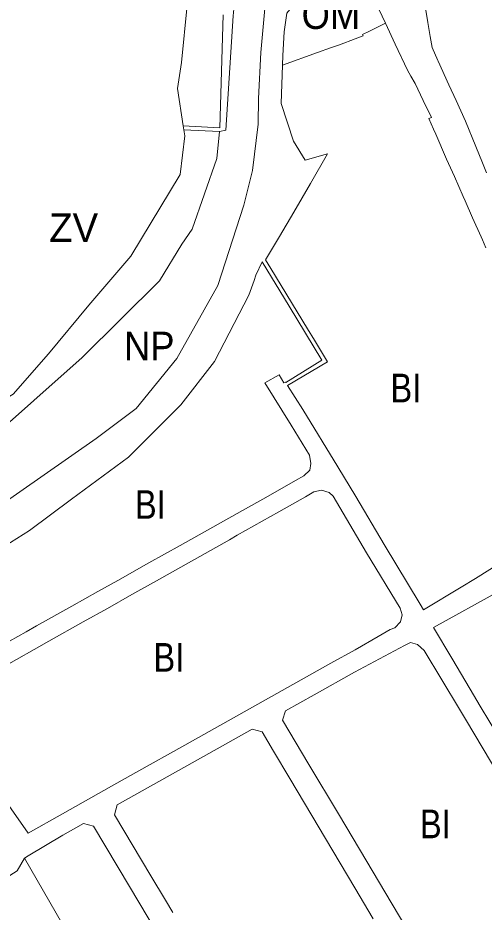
# Model space of a CAD drawing. Extents: x -650451 to -642268, y -1075216 to -1066610.
# Drawn here: x -646131.4 to -645935.9, y -1070484.4 to -1070109.3 of the extents above; entities that cross this region are included whole.
import ezdxf

# ---------------------------------------------------------------- set-up
doc = ezdxf.new("R2010")
doc.units = 0
doc.header["$LTSCALE"] = 4.8
for name, color, linetype, lineweight in [('1', 7, 'Continuous', 13), ('12', 7, 'Continuous', 13), ('15', 7, 'Continuous', 13), ('2', 7, 'Continuous', 13), ('24', 7, 'Continuous', 13), ('40', 7, 'Continuous', 13), ('45', 7, 'Continuous', 13), ('48', 7, 'Continuous', 13)]:
    doc.layers.add(name, color=color, linetype=linetype, lineweight=lineweight)
doc.layers.add('62', color=7, linetype='Continuous')

msp = doc.modelspace()

# ---------------------------------------------------------------- linework, layer by layer
at = {"layer": '1'}
for points in [[(-646164.402, -1070484.923), (-646164.216, -1070484.38), (-646164.005, -1070483.851), (-646163.769, -1070483.337), (-646163.51, -1070482.84), (-646161.74, -1070481.82), (-646156.91, -1070483.01), (-646134.79, -1070469.05), (-646131.7, -1070467.11), (-646128.68, -1070461.77)], [(-646128.68, -1070461.77), (-646112.64, -1070489.39), (-646100.45, -1070509.84), (-646087.81, -1070531.49), (-646077.92, -1070548.62), (-646061.11, -1070577.5), (-646060.88, -1070577.9)]]:
    msp.add_lwpolyline(points, dxfattribs=at)
at = {"layer": '12'}
for points in [[(-646020.39, -1070129.18), (-646020.23, -1070125.05), (-646019.71, -1070115.15), (-646018.64, -1070107.32), (-646014.13, -1070101.92), (-646006.74, -1070098.07), (-646002.8, -1070097.37), (-645992.6, -1070095.69), (-645985.08, -1070094.46)], [(-645985.08, -1070094.46), (-645984.1, -1070097.01), (-645977.22, -1070111.51)], [(-645977.22, -1070111.51), (-645983.92, -1070114.9), (-645986.83, -1070116.33), (-645986.61, -1070116.88), (-645989.89, -1070118.09), (-645996.56, -1070120.56), (-646000.31, -1070121.94), (-646005.76, -1070123.86), (-646020.39, -1070129.18)]]:
    msp.add_lwpolyline(points, dxfattribs=at)
at = {"layer": '15'}
for points in [[(-646159.26, -1070328.75), (-646152.57, -1070323.39), (-646098.57, -1070285.71), (-646081.74, -1070273.1), (-646064.78, -1070252.22), (-646047.55, -1070221.59), (-646036.61, -1070187.84), (-646033.06, -1070173.32), (-646030.66, -1070153.86), (-646030.51, -1070143.17), (-646029.45, -1070123.88), (-646027.66, -1070103.79), (-646016.12, -1070093.28), (-646003.08, -1070088.07), (-645995.59, -1070086.74), (-646003.18, -1070084.88), (-646023.84, -1070078.03), (-646027.71, -1070080.48)], [(-646027.71, -1070080.48), (-646032.79, -1070084.73), (-646040.05, -1070097.06), (-646041.14, -1070108.39), (-646044.21, -1070156.41), (-646046.84, -1070157.03), (-646061.8, -1070156.29), (-646062.06, -1070154.56)], [(-645985.08, -1070094.46), (-645992.6, -1070095.69), (-646002.8, -1070097.37), (-646006.74, -1070098.07), (-646014.13, -1070101.92), (-646018.64, -1070107.32), (-646019.71, -1070115.15), (-646020.23, -1070125.05), (-646020.39, -1070129.18)], [(-646062.06, -1070154.56), (-646046.76, -1070155.43), (-646045.35, -1070108.04)], [(-646020.39, -1070129.18), (-646021, -1070145.27), (-646015.86, -1070161.08), (-646010.94, -1070168.93), (-646001.55, -1070166.34), (-646008.75, -1070178.83), (-646015.63, -1070190.78), (-646021.68, -1070200.97), (-646027.5, -1070210.78), (-646025.32, -1070214.44), (-646009.96, -1070239.67), (-646006.95, -1070244.46), (-646001.55, -1070253.52), (-646018.27, -1070263.54), (-646011.89, -1070273.62), (-645997.17, -1070297.57), (-645989.72, -1070310.12), (-645977.73, -1070330.16), (-645962.69, -1070355.25), (-645961.29, -1070357.59), (-645945.44, -1070348.04), (-645939.51, -1070344.47), (-645927.52, -1070336.95)], [(-646170.01, -1070390.33), (-646127.93, -1070366.76), (-646123.57, -1070364.32), (-646108.74, -1070356.01), (-646097.91, -1070349.95), (-646089.54, -1070345.26), (-646076.45, -1070337.93), (-646063.37, -1070330.6), (-646037.19, -1070315.94), (-646027.47, -1070310.49), (-646014.98, -1070303.38), (-646011.51, -1070301.37), (-646008.91, -1070299.03), (-646008.5, -1070296.25), (-646009.17, -1070292.79), (-646016.79, -1070280.17), (-646027.85, -1070262.42), (-646021.85, -1070259.08), (-646019.81, -1070262.45), (-646019.19, -1070262.09), (-646019.06, -1070262.29), (-646003.89, -1070252.88), (-646017.67, -1070230.24), (-646029, -1070211.63), (-646031.59, -1070217.26), (-646032.36, -1070219.45), (-646034.53, -1070225.58), (-646048.94, -1070253.4), (-646063.14, -1070271.56), (-646084.97, -1070293.57), (-646108.9, -1070311.25), (-646126.59, -1070324.33), (-646145.23, -1070336)], [(-646139.26, -1070434.03), (-646127.15, -1070451.21), (-646112.7, -1070443.12), (-646092.13, -1070431.59), (-646081.95, -1070425.89), (-646061.44, -1070414.39), (-646030.8, -1070397.2), (-646010.35, -1070385.73), (-646000.1, -1070379.99), (-645989.89, -1070374.31), (-645980.32, -1070368.8), (-645975.27, -1070365.89), (-645973.25, -1070365.19), (-645970.88, -1070362.62), (-645970.25, -1070359.71), (-645971.03, -1070356.94), (-645985.26, -1070333.71), (-645999.24, -1070309.95), (-646000.86, -1070308.34), (-646004.04, -1070307.45), (-646007.34, -1070308.14), (-646010.74, -1070310.17), (-646021.94, -1070316.43), (-646039.46, -1070326.33), (-646042.72, -1070328.18), (-646063.09, -1070339.69), (-646073.33, -1070345.44), (-646083.62, -1070351.23), (-646093.88, -1070356.98), (-646103.98, -1070362.66), (-646118.41, -1070370.76), (-646124.65, -1070374.27), (-646139.51, -1070382.62)], [(-645929.29, -1070349.59), (-645957.06, -1070365.02), (-645949.43, -1070377.9), (-645941.77, -1070390.84), (-645937.48, -1070398), (-645929.43, -1070411.46)], [(-645886.41, -1070498.83), (-645887.31, -1070497.33), (-645897.23, -1070480.83), (-645900.37, -1070475.61), (-645909.07, -1070461.12), (-645921.5, -1070440.43), (-645930.78, -1070425), (-645932.75, -1070421.72), (-645943.71, -1070403.5), (-645946.22, -1070399.32), (-645961.01, -1070374.71), (-645963.76, -1070372.18), (-645966.73, -1070371.37), (-645969.23, -1070372.54), (-645990.19, -1070383.7), (-646007.11, -1070393.19), (-646019.14, -1070399.94), (-646020.36, -1070403.89), (-646009.33, -1070422.47), (-645997, -1070443.23), (-645985.06, -1070463.18), (-645974.83, -1070480.36), (-645953.43, -1070516.32), (-645941.2, -1070537.55)], [(-645982.42, -1070487.26), (-645990.13, -1070474.19), (-645993.19, -1070469.06), (-646017.38, -1070428.4), (-646024.17, -1070416.95), (-646029, -1070408.81), (-646033.15, -1070407.7), (-646053.6, -1070419.15), (-646089.82, -1070439.46), (-646090.87, -1070443.56), (-646075.66, -1070469.14), (-646069.52, -1070479.44), (-646066.46, -1070484.59)], [(-646053.24, -1070590.92), (-646052.04, -1070592.97), (-646036.87, -1070618.77), (-646021.42, -1070603.75), (-646012.27, -1070594.86), (-646030.57, -1070564.36), (-646033.35, -1070565.62), (-646032.15, -1070561.72), (-646043.14, -1070543.4), (-646049.88, -1070532.17), (-646057.56, -1070519.23), (-646060.12, -1070514.91), (-646064.7, -1070507.17), (-646070.55, -1070497.27), (-646072.85, -1070493.39), (-646084.62, -1070473.63), (-646099.67, -1070448.37), (-646103.83, -1070447.25), (-646112.55, -1070452.14), (-646127.09, -1070460.84), (-646128.68, -1070461.77)], [(-646128.68, -1070461.77), (-646131.7, -1070467.11), (-646134.79, -1070469.05), (-646156.91, -1070483.01), (-646161.74, -1070481.82), (-646163.51, -1070482.84), (-646163.769, -1070483.337), (-646164.005, -1070483.851), (-646164.216, -1070484.38), (-646164.402, -1070484.923)]]:
    msp.add_lwpolyline(points, dxfattribs=at)
at = {"layer": '2'}
for points in [[(-645934.81, -1070174.36), (-645936.3, -1070170.74), (-645936.57, -1070170.09), (-645939.36, -1070163.29), (-645943.7, -1070152.62), (-645947.63, -1070144.02), (-645950.6, -1070137.43), (-645955.07, -1070127.5), (-645955.23, -1070127.14), (-645957.7, -1070121.77), (-645958.45, -1070117.18), (-645959.4, -1070111.28), (-645961.65, -1070097.54)], [(-646020.39, -1070129.18), (-646005.76, -1070123.86), (-646000.31, -1070121.94), (-645996.56, -1070120.56), (-645989.89, -1070118.09), (-645986.61, -1070116.88), (-645986.83, -1070116.33), (-645983.92, -1070114.9), (-645977.22, -1070111.51)], [(-645977.22, -1070111.51), (-645973.11, -1070120.3), (-645968.02, -1070131.18), (-645966.53, -1070133.78), (-645964.79, -1070136.9), (-645961.36, -1070144), (-645957.96, -1070151.1), (-645958.99, -1070151.56), (-645957.09, -1070155.97), (-645956.17, -1070158.1), (-645951.58, -1070168.55), (-645948.35, -1070175.83), (-645944.71, -1070184.17), (-645943.86, -1070186.04), (-645940.68, -1070193.11), (-645937.14, -1070201.19), (-645936.58, -1070202.44), (-645935.11, -1070205.74)], [(-645927.52, -1070336.95), (-645939.51, -1070344.47), (-645945.44, -1070348.04), (-645961.29, -1070357.59), (-645962.69, -1070355.25), (-645977.73, -1070330.16), (-645989.72, -1070310.12), (-645997.17, -1070297.57), (-646011.89, -1070273.62), (-646018.27, -1070263.54), (-646001.55, -1070253.52), (-646006.95, -1070244.46), (-646009.96, -1070239.67), (-646025.32, -1070214.44), (-646027.5, -1070210.78), (-646021.68, -1070200.97), (-646015.63, -1070190.78), (-646008.75, -1070178.83), (-646001.55, -1070166.34), (-646010.94, -1070168.93), (-646015.86, -1070161.08), (-646021, -1070145.27), (-646020.39, -1070129.18)], [(-646145.23, -1070336), (-646126.59, -1070324.33), (-646108.9, -1070311.25), (-646084.97, -1070293.57), (-646063.14, -1070271.56), (-646048.94, -1070253.4), (-646034.53, -1070225.58), (-646032.36, -1070219.45), (-646031.59, -1070217.26), (-646029, -1070211.63), (-646017.67, -1070230.24), (-646003.89, -1070252.88), (-646019.06, -1070262.29), (-646019.19, -1070262.09), (-646019.81, -1070262.45), (-646021.85, -1070259.08), (-646027.85, -1070262.42), (-646016.79, -1070280.17), (-646009.17, -1070292.79), (-646008.5, -1070296.25), (-646008.91, -1070299.03), (-646011.51, -1070301.37), (-646014.98, -1070303.38), (-646027.47, -1070310.49), (-646037.19, -1070315.94), (-646063.37, -1070330.6), (-646076.45, -1070337.93), (-646089.54, -1070345.26), (-646097.91, -1070349.95), (-646108.74, -1070356.01), (-646123.57, -1070364.32), (-646127.93, -1070366.76), (-646170.01, -1070390.33)], [(-646139.51, -1070382.62), (-646124.65, -1070374.27), (-646118.41, -1070370.76), (-646103.98, -1070362.66), (-646093.88, -1070356.98), (-646083.62, -1070351.23), (-646073.33, -1070345.44), (-646063.09, -1070339.69), (-646042.72, -1070328.18), (-646039.46, -1070326.33), (-646021.94, -1070316.43), (-646010.74, -1070310.17), (-646007.34, -1070308.14), (-646004.04, -1070307.45), (-646000.86, -1070308.34), (-645999.24, -1070309.95), (-645985.26, -1070333.71), (-645971.03, -1070356.94), (-645970.25, -1070359.71), (-645970.88, -1070362.62), (-645973.25, -1070365.19), (-645975.27, -1070365.89), (-645980.32, -1070368.8), (-645989.89, -1070374.31), (-646000.1, -1070379.99), (-646010.35, -1070385.73), (-646030.8, -1070397.2), (-646061.44, -1070414.39), (-646081.95, -1070425.89), (-646092.13, -1070431.59), (-646112.7, -1070443.12), (-646127.15, -1070451.21), (-646139.26, -1070434.03)], [(-645929.43, -1070411.46), (-645937.48, -1070398), (-645941.77, -1070390.84), (-645949.43, -1070377.9), (-645957.06, -1070365.02), (-645929.29, -1070349.59)], [(-645941.2, -1070537.55), (-645953.43, -1070516.32), (-645974.83, -1070480.36), (-645985.06, -1070463.18), (-645997, -1070443.23), (-646009.33, -1070422.47), (-646020.36, -1070403.89), (-646019.14, -1070399.94), (-646007.11, -1070393.19), (-645990.19, -1070383.7), (-645969.23, -1070372.54), (-645966.73, -1070371.37), (-645963.76, -1070372.18), (-645961.01, -1070374.71), (-645946.22, -1070399.32), (-645943.71, -1070403.5), (-645932.75, -1070421.72), (-645930.78, -1070425), (-645921.5, -1070440.43), (-645909.07, -1070461.12), (-645900.37, -1070475.61), (-645897.23, -1070480.83), (-645887.31, -1070497.33), (-645886.41, -1070498.83)], [(-646066.46, -1070484.59), (-646069.52, -1070479.44), (-646075.66, -1070469.14), (-646090.87, -1070443.56), (-646089.82, -1070439.46), (-646053.6, -1070419.15), (-646033.15, -1070407.7), (-646029, -1070408.81), (-646024.17, -1070416.95), (-646017.38, -1070428.4), (-645993.19, -1070469.06), (-645990.13, -1070474.19), (-645982.42, -1070487.26)], [(-646128.68, -1070461.77), (-646127.09, -1070460.84), (-646112.55, -1070452.14), (-646103.83, -1070447.25), (-646099.67, -1070448.37), (-646084.62, -1070473.63), (-646072.85, -1070493.39), (-646070.55, -1070497.27), (-646064.7, -1070507.17), (-646060.12, -1070514.91), (-646057.56, -1070519.23), (-646049.88, -1070532.17), (-646043.14, -1070543.4), (-646032.15, -1070561.72), (-646033.35, -1070565.62), (-646030.57, -1070564.36), (-646012.27, -1070594.86), (-646021.42, -1070603.75), (-646036.87, -1070618.77), (-646052.04, -1070592.97), (-646053.24, -1070590.92), (-646060.88, -1070577.9)], [(-646060.88, -1070577.9), (-646061.11, -1070577.5), (-646077.92, -1070548.62), (-646087.81, -1070531.49), (-646100.45, -1070509.84), (-646112.64, -1070489.39), (-646128.68, -1070461.77)]]:
    msp.add_lwpolyline(points, dxfattribs=at)
at = {"layer": '24'}
for points in [[(-645977.22, -1070111.51), (-645984.1, -1070097.01), (-645985.08, -1070094.46)], [(-645961.65, -1070097.54), (-645959.4, -1070111.28), (-645958.45, -1070117.18), (-645957.7, -1070121.77), (-645955.23, -1070127.14), (-645955.07, -1070127.5), (-645950.6, -1070137.43), (-645947.63, -1070144.02), (-645943.7, -1070152.62), (-645939.36, -1070163.29), (-645936.57, -1070170.09), (-645936.3, -1070170.74), (-645934.81, -1070174.36)], [(-645935.11, -1070205.74), (-645936.58, -1070202.44), (-645937.14, -1070201.19), (-645940.68, -1070193.11), (-645943.86, -1070186.04), (-645944.71, -1070184.17), (-645948.35, -1070175.83), (-645951.58, -1070168.55), (-645956.17, -1070158.1), (-645957.09, -1070155.97), (-645958.99, -1070151.56), (-645957.96, -1070151.1), (-645961.36, -1070144), (-645964.79, -1070136.9), (-645966.53, -1070133.78), (-645968.02, -1070131.18), (-645973.11, -1070120.3), (-645977.22, -1070111.51)]]:
    msp.add_lwpolyline(points, dxfattribs=at)
at = {"layer": '40'}
for points in [[(-646056.09, -1070055.76), (-646060.36, -1070103.99), (-646062.8, -1070128.04), (-646064.44, -1070138.99), (-646062.06, -1070154.56), (-646061.8, -1070156.29)], [(-646061.8, -1070156.29), (-646061.41, -1070158.85), (-646063.42, -1070175.01), (-646084.06, -1070209.26), (-646101.61, -1070229.78), (-646118.58, -1070250.17), (-646133.33, -1070267.1), (-646156.17, -1070280.5), (-646174.12, -1070280.47), (-646206.77, -1070269.12), (-646210.38, -1070267.68)]]:
    msp.add_lwpolyline(points, dxfattribs=at)
at = {"layer": '45'}
for points in [[(-646062.06, -1070154.56), (-646064.44, -1070138.99), (-646062.8, -1070128.04), (-646060.36, -1070103.99), (-646056.09, -1070055.76)], [(-646045.35, -1070108.04), (-646046.76, -1070155.43), (-646062.06, -1070154.56)], [(-646210.38, -1070267.68), (-646206.77, -1070269.12), (-646174.12, -1070280.47), (-646156.17, -1070280.5), (-646133.33, -1070267.1), (-646118.58, -1070250.17), (-646101.61, -1070229.78), (-646084.06, -1070209.26), (-646063.42, -1070175.01), (-646061.41, -1070158.85), (-646061.8, -1070156.29), (-646046.84, -1070157.03)], [(-646046.84, -1070157.03), (-646047.97, -1070168.31), (-646058.29, -1070197.88), (-646062.69, -1070204.21), (-646072.06, -1070219.56), (-646104.49, -1070251.8), (-646145.19, -1070287.85), (-646168.86, -1070291.34), (-646203.06, -1070281.27), (-646228.96, -1070273.65), (-646235.69, -1070273.19), (-646240.68, -1070272.84), (-646265.2, -1070280.49), (-646302.98, -1070303.43), (-646313.77, -1070309.99), (-646359.41, -1070334.2), (-646391.97, -1070362.11), (-646415.34, -1070392.15), (-646478.77, -1070449), (-646505.87, -1070462.81), (-646524.86, -1070460.39), (-646575.64, -1070436.46), (-646588.54, -1070434.24), (-646599.32, -1070439.31)]]:
    msp.add_lwpolyline(points, dxfattribs=at)
at = {"layer": '48'}
for points in [[(-646023.84, -1070078.03), (-646003.18, -1070084.88), (-645995.59, -1070086.74), (-646003.08, -1070088.07), (-646016.12, -1070093.28), (-646027.66, -1070103.79), (-646029.45, -1070123.88), (-646030.51, -1070143.17), (-646030.66, -1070153.86), (-646033.06, -1070173.32), (-646036.61, -1070187.84), (-646047.55, -1070221.59), (-646064.78, -1070252.22), (-646081.74, -1070273.1), (-646098.57, -1070285.71), (-646152.57, -1070323.39), (-646159.26, -1070328.75)], [(-646046.84, -1070157.03), (-646044.21, -1070156.41), (-646041.14, -1070108.39), (-646040.05, -1070097.06), (-646032.79, -1070084.73), (-646027.71, -1070080.48)], [(-646599.32, -1070439.31), (-646588.54, -1070434.24), (-646575.64, -1070436.46), (-646524.86, -1070460.39), (-646505.87, -1070462.81), (-646478.77, -1070449), (-646415.34, -1070392.15), (-646391.97, -1070362.11), (-646359.41, -1070334.2), (-646313.77, -1070309.99), (-646302.98, -1070303.43), (-646265.2, -1070280.49), (-646240.68, -1070272.84), (-646235.69, -1070273.19), (-646228.96, -1070273.65), (-646203.06, -1070281.27), (-646168.86, -1070291.34), (-646145.19, -1070287.85), (-646104.49, -1070251.8), (-646072.06, -1070219.56), (-646062.69, -1070204.21), (-646058.29, -1070197.88), (-646047.97, -1070168.31), (-646046.84, -1070157.03)]]:
    msp.add_lwpolyline(points, dxfattribs=at)

# ---------------------------------------------------------------- texts
at = {"layer": '62'}
for s, width, p in [('OM', 0.95, (-646012.403, -1070113.953)), ('NP', 0.95, (-646086.9, -1070252.944)), ('BI', 0.85, (-645975.131, -1070270.571)), ('BI', 0.85, (-646082.312, -1070319.417)), ('BI', 0.85, (-646074.539, -1070383.545)), ('BI', 0.85, (-645962.768, -1070453.416))]:
    msp.add_text(s, height=12, dxfattribs=dict(at, width=width)).set_placement(p)
msp.add_text('ZV', height=12, dxfattribs=at).set_placement((-646118.275, -1070203.31))

doc.saveas('drawing.dxf')
